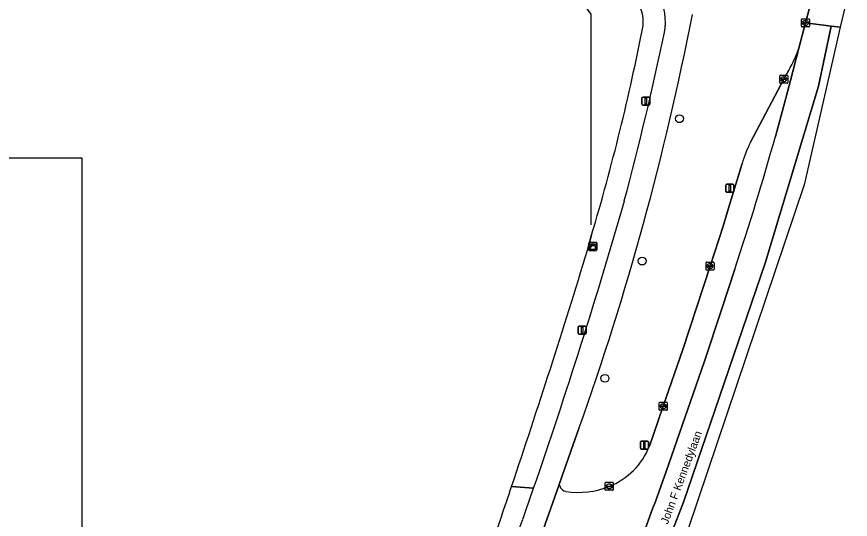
# Model space of a CAD drawing. Extents: x 161241 to 161758, y 384138 to 384885.
# Drawn here: x 161642.2 to 161746.4, y 384754.7 to 384817.5 of the extents above; entities that cross this region are included whole.
import ezdxf

# ---------------------------------------------------------------- set-up
doc = ezdxf.new("R2010")
doc.units = 0
for name, color, linetype in [('IMGEO_Berm_groen', 7, 'Continuous'), ('IMGEO_Boom', 7, 'Continuous'), ('IMGEO_Erf', 7, 'Continuous'), ('IMGEO_Fietspad_gesloten', 7, 'Continuous'), ('IMGEO_Hek', 7, 'Continuous'), ('IMGEO_Kast', 7, 'Continuous'), ('IMGEO_Kolk', 7, 'Continuous'), ('IMGEO_Lichtmast', 7, 'Continuous'), ('IMGEO_Openbare_ruimte_label', 7, 'Continuous'), ('IMGEO_Pand_vergunning_verleend', 7, 'Continuous'), ('IMGEO_Rijbaan_lokaal_gesloten', 7, 'Continuous'), ('IMGEO_Rijbaan_lokaal_open', 7, 'Continuous'), ('IMGEO_Voetpad_open', 7, 'Continuous')]:
    doc.layers.add(name, color=color, linetype=linetype)

msp = doc.modelspace()

# ---------------------------------------------------------------- linework, layer by layer
at = {"layer": 'IMGEO_Berm_groen'}
for points in [[(161740, 384813.52), (161740.82, 384816.69), (161741.28, 384818.41)], [(161733.96, 384801.79), (161738.1, 384809.65), (161738.74, 384810.76)], [(161730.54, 384791.27), (161731.21, 384793.52), (161732.89, 384799.1)], [(161721.31, 384763.82), (161723.04, 384768.79), (161725.49, 384775.9), (161728.89, 384786.3), (161730.54, 384791.27)], [(161712.5, 384766.02), (161710.46, 384760.22), (161709.99, 384758.88), (161710.1, 384758.84)]]:
    msp.add_lwpolyline(points, dxfattribs=at)
for centre, radius, start, end in [((161376.64, 384885.92), 356.62, 340.3527, 348.9764), ((161723.94, 384819.15), 17.01, 330.4533, 340.6775), ((161747.83, 384794.77), 15.55, 153.1574, 163.8286), ((161713, 384767.08), 8.93, 291.639, 338.5775), ((161710.99, 384759.08), 0.921, 194.8928, 263.401), ((161712.5, 384767.94), 9.91, 260.628, 292.4989)]:
    msp.add_arc(centre, radius, start, end, dxfattribs=at)
at = {"layer": 'IMGEO_Boom'}
for centre in [(161725.07, 384804.71), (161720.41, 384786.93), (161715.75, 384772.28)]:
    msp.add_circle(centre, 0.489, dxfattribs=at)
at = {"layer": 'IMGEO_Erf'}
msp.add_lwpolyline([(161713.58, 384788.28), (161714.08, 384790.19)], dxfattribs=at)
for centre, radius, start, end in [((161715.38, 384816.78), 5.16, 355.4845, 65.2299), ((161448.91, 384869.35), 276.74, 343.3794, 348.9636), ((160652.55, 385113.2), 1109.66, 341.37217, 342.97397), ((160591.97, 385133.79), 1173.65, 340.97507, 341.36439)]:
    msp.add_arc(centre, radius, start, end, dxfattribs=at)
at = {"layer": 'IMGEO_Fietspad_gesloten'}
msp.add_lwpolyline([(161707.05, 384750.51), (161709.99, 384758.88), (161710.46, 384760.22), (161712.5, 384766.02)], dxfattribs=at)
for centre, radius, start, end in [((161715.17, 384816.77), 8.14, 350.8431, 58.2286), ((161376.64, 384885.92), 356.62, 340.3527, 348.9764), ((161325, 384899.29), 406.92, 345.0675, 348.1139), ((161030.54, 384992.23), 715.53, 340.93948, 343.95298), ((161038.18, 384989.52), 707.42, 340.61079, 340.94437), ((160913.04, 385019.97), 835.67, 341.22596, 341.48978)]:
    msp.add_arc(centre, radius, start, end, dxfattribs=at)
at = {"layer": 'IMGEO_Hek'}
msp.add_lwpolyline([(161709.2, 384824.32), (161714, 384817.76), (161713.99, 384791.46)], dxfattribs=at)
at = {"layer": 'IMGEO_Kast'}
for p, q in [((161713.81, 384789.26), (161714.65, 384789.26)), ((161714.65, 384789.26), (161713.81, 384789.26)), ((161713.74, 384788.34), (161713.74, 384789.18)), ((161713.74, 384789.18), (161713.74, 384788.34)), ((161714.66, 384788.26), (161713.82, 384788.26)), ((161713.82, 384788.26), (161714.66, 384788.26)), ((161714.74, 384789.19), (161714.74, 384788.35)), ((161714.74, 384788.35), (161714.74, 384789.19))]:
    msp.add_line(p, q, dxfattribs=at)
for points in [[(161713.93, 384789.05), (161714.53, 384789.05), (161714.53, 384788.97), (161713.93, 384788.97), (161713.93, 384789.05)], [(161713.93, 384788.88), (161714.53, 384788.88), (161714.53, 384788.39), (161713.93, 384788.39), (161713.93, 384788.88)]]:
    msp.add_lwpolyline(points, dxfattribs=at)
msp.add_circle((161714.02, 384788.72), 0.0377, dxfattribs=at)
for centre, start, end in [((161713.82, 384789.18), 92.4484, 184.2845), ((161713.82, 384789.18), 92.4484, 184.2845), ((161714.66, 384789.18), 2.4484, 94.2845), ((161714.66, 384789.18), 2.4484, 94.2845), ((161713.82, 384788.34), 182.4484, 274.2845), ((161713.82, 384788.34), 182.4484, 274.2845), ((161714.66, 384788.34), 272.4484, 4.2845), ((161714.66, 384788.34), 272.4484, 4.2845)]:
    msp.add_arc(centre, 0.0779, start, end, dxfattribs=at)
at = {"layer": 'IMGEO_Kolk'}
for p, q in [((161740.32, 384816.26), (161740.32, 384817.11)), ((161740.39, 384817.19), (161741.24, 384817.19)), ((161740.58, 384816.68), (161740.58, 384816.69)), ((161740.62, 384816.73), (161741.02, 384816.73)), ((161741.01, 384816.64), (161740.62, 384816.64)), ((161740.83, 384816.41), (161740.8, 384816.41)), ((161740.81, 384816.97), (161740.83, 384816.97)), ((161741.06, 384816.69), (161741.06, 384816.68)), ((161741.32, 384817.11), (161741.32, 384816.26)), ((161741.24, 384816.19), (161740.39, 384816.19)), ((161737.6, 384809.22), (161737.6, 384810.08)), ((161737.68, 384810.15), (161738.53, 384810.15)), ((161738.6, 384810.08), (161738.6, 384809.22)), ((161738.53, 384809.15), (161737.68, 384809.15)), ((161737.86, 384809.64), (161737.86, 384809.66)), ((161737.9, 384809.69), (161738.3, 384809.69)), ((161738.3, 384809.61), (161737.9, 384809.61)), ((161738.09, 384809.93), (161738.12, 384809.93)), ((161738.11, 384809.37), (161738.09, 384809.37)), ((161738.35, 384809.66), (161738.35, 384809.64)), ((161728.39, 384785.88), (161728.39, 384786.73)), ((161728.46, 384786.8), (161729.31, 384786.8)), ((161728.64, 384786.3), (161728.64, 384786.31)), ((161729.08, 384786.26), (161728.68, 384786.26)), ((161728.69, 384786.35), (161729.08, 384786.35)), ((161728.87, 384786.58), (161728.9, 384786.58)), ((161729.13, 384786.31), (161729.13, 384786.3)), ((161729.39, 384786.73), (161729.39, 384785.88)), ((161729.31, 384785.8), (161728.46, 384785.8)), ((161728.9, 384786.02), (161728.87, 384786.02)), ((161722.54, 384768.36), (161722.54, 384769.22)), ((161722.61, 384769.29), (161723.47, 384769.29)), ((161722.8, 384768.78), (161722.8, 384768.8)), ((161722.84, 384768.83), (161723.24, 384768.83)), ((161723.24, 384768.75), (161722.84, 384768.75)), ((161723.03, 384769.07), (161723.05, 384769.07)), ((161723.05, 384768.51), (161723.03, 384768.51)), ((161723.28, 384768.8), (161723.28, 384768.78)), ((161723.54, 384769.22), (161723.54, 384768.36)), ((161723.47, 384768.29), (161722.61, 384768.29)), ((161715.79, 384758.36), (161715.79, 384759.21)), ((161715.86, 384759.29), (161716.71, 384759.29)), ((161716.28, 384759.07), (161716.3, 384759.07)), ((161716.79, 384759.21), (161716.79, 384758.36)), ((161716.71, 384758.29), (161715.86, 384758.29)), ((161716.05, 384758.78), (161716.05, 384758.79)), ((161716.09, 384758.83), (161716.49, 384758.83)), ((161716.48, 384758.74), (161716.09, 384758.74)), ((161716.3, 384758.51), (161716.27, 384758.51)), ((161716.53, 384758.79), (161716.53, 384758.78))]:
    msp.add_line(p, q, dxfattribs=at)
for points in [[(161740.32, 384816.26), (161740.32, 384817.11)], [(161740.39, 384817.19), (161741.24, 384817.19)], [(161741.32, 384817.11), (161741.32, 384816.26)], [(161741.24, 384816.19), (161740.39, 384816.19)], [(161737.6, 384809.22), (161737.6, 384810.08)], [(161737.68, 384810.15), (161738.53, 384810.15)], [(161738.6, 384810.08), (161738.6, 384809.22)], [(161738.53, 384809.15), (161737.68, 384809.15)], [(161728.39, 384785.88), (161728.39, 384786.73)], [(161728.46, 384786.8), (161729.31, 384786.8)], [(161729.39, 384786.73), (161729.39, 384785.88)], [(161729.31, 384785.8), (161728.46, 384785.8)], [(161722.54, 384768.36), (161722.54, 384769.22)], [(161722.61, 384769.29), (161723.47, 384769.29)], [(161723.54, 384769.22), (161723.54, 384768.36)], [(161723.47, 384768.29), (161722.61, 384768.29)], [(161715.79, 384758.36), (161715.79, 384759.21)], [(161715.86, 384759.29), (161716.71, 384759.29)], [(161716.79, 384759.21), (161716.79, 384758.36)], [(161716.71, 384758.29), (161715.86, 384758.29)]]:
    msp.add_lwpolyline(points, dxfattribs=at)
for centre, radius, start, end in [((161740.39, 384817.11), 0.0765, 91.552, 178.448), ((161740.39, 384817.11), 0.0765, 91.552, 178.448), ((161740.62, 384816.69), 0.0403, 85.8775, 175.7526), ((161740.61, 384816.68), 0.0366, 178.938, 274.7102), ((161741.02, 384816.69), 0.043, 264.8664, 352.4533), ((161741.02, 384816.69), 0.0386, 1.7309, 96.639), ((161741.24, 384817.11), 0.0765, 1.552, 88.448), ((161741.24, 384817.11), 0.0765, 1.552, 88.448), ((161740.39, 384816.26), 0.0765, 181.552, 268.448), ((161740.39, 384816.26), 0.0765, 181.552, 268.448), ((161741.24, 384816.26), 0.0765, 271.552, 358.448), ((161741.24, 384816.26), 0.0765, 271.552, 358.448), ((161737.68, 384810.07), 0.0765, 91.552, 178.448), ((161737.68, 384810.07), 0.0765, 91.552, 178.448), ((161738.53, 384810.07), 0.0765, 1.552, 88.448), ((161738.53, 384810.07), 0.0765, 1.552, 88.448), ((161737.68, 384809.22), 0.0765, 181.552, 268.448), ((161737.68, 384809.22), 0.0765, 181.552, 268.448), ((161737.9, 384809.65), 0.0403, 85.8775, 175.7526), ((161737.9, 384809.64), 0.0366, 178.938, 274.7102), ((161738.31, 384809.65), 0.0386, 1.7309, 96.639), ((161738.3, 384809.65), 0.043, 264.8664, 352.4533), ((161738.53, 384809.22), 0.0765, 271.552, 358.448), ((161738.53, 384809.22), 0.0765, 271.552, 358.448), ((161728.46, 384786.73), 0.0765, 91.552, 178.448), ((161728.46, 384786.73), 0.0765, 91.552, 178.448), ((161728.68, 384786.31), 0.0403, 85.8775, 175.7526), ((161728.68, 384786.3), 0.0366, 178.938, 274.7102), ((161729.09, 384786.31), 0.0386, 1.7309, 96.639), ((161729.09, 384786.3), 0.043, 264.8664, 352.4533), ((161729.31, 384786.73), 0.0765, 1.552, 88.448), ((161729.31, 384786.73), 0.0765, 1.552, 88.448), ((161728.46, 384785.88), 0.0765, 181.552, 268.448), ((161728.46, 384785.88), 0.0765, 181.552, 268.448), ((161729.31, 384785.88), 0.0765, 271.552, 358.448), ((161729.31, 384785.88), 0.0765, 271.552, 358.448), ((161722.62, 384769.22), 0.0765, 91.552, 178.448), ((161722.62, 384769.22), 0.0765, 91.552, 178.448), ((161722.84, 384768.79), 0.0403, 85.8775, 175.7526), ((161722.84, 384768.78), 0.0366, 178.938, 274.7102), ((161723.24, 384768.8), 0.0386, 1.7309, 96.639), ((161723.24, 384768.79), 0.043, 264.8664, 352.4533), ((161723.46, 384769.22), 0.0765, 1.552, 88.448), ((161723.46, 384769.22), 0.0765, 1.552, 88.448), ((161722.62, 384768.37), 0.0765, 181.552, 268.448), ((161722.62, 384768.37), 0.0765, 181.552, 268.448), ((161723.46, 384768.37), 0.0765, 271.552, 358.448), ((161723.46, 384768.37), 0.0765, 271.552, 358.448), ((161715.86, 384759.21), 0.0765, 91.552, 178.448), ((161715.86, 384759.21), 0.0765, 91.552, 178.448), ((161716.71, 384759.21), 0.0765, 1.552, 88.448), ((161716.71, 384759.21), 0.0765, 1.552, 88.448), ((161715.86, 384758.36), 0.0765, 181.552, 268.448), ((161715.86, 384758.36), 0.0765, 181.552, 268.448), ((161716.09, 384758.79), 0.0403, 85.8775, 175.7526), ((161716.08, 384758.78), 0.0366, 178.938, 274.7102), ((161716.49, 384758.79), 0.043, 264.8664, 352.4533), ((161716.49, 384758.79), 0.0386, 1.7309, 96.639), ((161716.71, 384758.36), 0.0765, 271.552, 358.448), ((161716.71, 384758.36), 0.0765, 271.552, 358.448)]:
    msp.add_arc(centre, radius, start, end, dxfattribs=at)
for centre, major_axis, ratio, start_param, end_param in [((161740.8, 384816.69), (-0.387, 0.002), 0.722429, 4.712389, 7.853982), ((161740.83, 384816.69), (-0.39, 0.002), 0.717154, 1.570796, 4.712389), ((161738.09, 384809.65), (-0.387, 0.002), 0.722429, 4.712389, 7.853982), ((161738.11, 384809.65), (-0.39, 0.002), 0.717154, 1.570796, 4.712389), ((161728.87, 384786.3), (-0.387, 0.002), 0.722429, 4.712389, 7.853982), ((161728.9, 384786.3), (-0.39, 0.002), 0.717154, 1.570796, 4.712389), ((161723.03, 384768.79), (-0.387, 0.002), 0.722429, 4.712389, 7.853982), ((161723.05, 384768.79), (-0.39, 0.002), 0.717154, 1.570796, 4.712389), ((161716.27, 384758.79), (-0.387, 0.002), 0.722429, 4.712389, 7.853982), ((161716.3, 384758.79), (-0.39, 0.002), 0.717154, 1.570796, 4.712389)]:
    msp.add_ellipse(centre, major_axis=major_axis, ratio=ratio, start_param=start_param, end_param=end_param, dxfattribs=at)
at = {"layer": 'IMGEO_Lichtmast'}
for p, q in [((161720.38, 384806.51), (161720.38, 384807.31)), ((161720.38, 384807.31), (161720.38, 384806.51)), ((161720.48, 384807.41), (161721.27, 384807.41)), ((161721.27, 384807.41), (161720.48, 384807.41)), ((161721.37, 384807.31), (161721.37, 384806.51)), ((161721.37, 384806.51), (161721.37, 384807.31)), ((161721.27, 384806.41), (161720.48, 384806.41)), ((161720.48, 384806.41), (161721.27, 384806.41)), ((161730.96, 384796.52), (161731.75, 384796.52)), ((161731.75, 384796.52), (161730.96, 384796.52)), ((161730.86, 384795.62), (161730.86, 384796.42)), ((161730.86, 384796.42), (161730.86, 384795.62)), ((161731.75, 384795.52), (161730.96, 384795.52)), ((161730.96, 384795.52), (161731.75, 384795.52)), ((161731.85, 384796.42), (161731.85, 384795.62)), ((161731.85, 384795.62), (161731.85, 384796.42)), ((161712.51, 384778.8), (161713.3, 384778.8)), ((161713.3, 384778.8), (161712.51, 384778.8)), ((161712.41, 384777.9), (161712.41, 384778.7)), ((161712.41, 384778.7), (161712.41, 384777.9)), ((161713.3, 384777.8), (161712.51, 384777.8)), ((161712.51, 384777.8), (161713.3, 384777.8)), ((161713.4, 384778.7), (161713.4, 384777.9)), ((161713.4, 384777.9), (161713.4, 384778.7)), ((161720.19, 384763.54), (161720.19, 384764.33)), ((161720.19, 384764.33), (161720.19, 384763.54)), ((161720.29, 384764.43), (161721.08, 384764.43)), ((161721.08, 384764.43), (161720.29, 384764.43)), ((161721.18, 384764.33), (161721.18, 384763.54)), ((161721.18, 384763.54), (161721.18, 384764.33)), ((161721.08, 384763.44), (161720.29, 384763.44)), ((161720.29, 384763.44), (161721.08, 384763.44))]:
    msp.add_line(p, q, dxfattribs=at)
for points in [[(161720.8, 384807.29), (161720.95, 384807.29), (161720.95, 384806.54), (161720.8, 384806.54), (161720.8, 384807.29)], [(161731.28, 384796.4), (161731.43, 384796.4), (161731.43, 384795.65), (161731.28, 384795.65), (161731.28, 384796.4)], [(161712.83, 384778.68), (161712.98, 384778.68), (161712.98, 384777.93), (161712.83, 384777.93), (161712.83, 384778.68)], [(161720.61, 384764.31), (161720.76, 384764.31), (161720.76, 384763.56), (161720.61, 384763.56), (161720.61, 384764.31)]]:
    msp.add_lwpolyline(points, dxfattribs=at)
for centre, start, end in [((161720.48, 384807.31), 90, 180), ((161720.48, 384807.31), 90, 180), ((161721.27, 384807.31), 0, 90), ((161721.27, 384807.31), 360, 90), ((161720.48, 384806.51), 180, 270), ((161720.48, 384806.51), 180, 270), ((161721.27, 384806.51), 270, 0), ((161721.27, 384806.51), 270, 0), ((161730.96, 384796.42), 90, 180), ((161730.96, 384796.42), 90, 180), ((161731.75, 384796.42), 0, 90), ((161731.75, 384796.42), 360, 90), ((161730.96, 384795.62), 180, 270), ((161730.96, 384795.62), 180, 270), ((161731.75, 384795.62), 270, 0), ((161731.75, 384795.62), 270, 0), ((161712.51, 384778.7), 90, 180), ((161712.51, 384778.7), 90, 180), ((161713.3, 384778.7), 0, 90), ((161713.3, 384778.7), 360, 90), ((161712.51, 384777.9), 180, 270), ((161712.51, 384777.9), 180, 270), ((161713.3, 384777.9), 270, 0), ((161713.3, 384777.9), 270, 0), ((161720.29, 384764.33), 90, 180), ((161720.29, 384764.33), 90, 180), ((161721.08, 384764.33), 0, 90), ((161721.08, 384764.33), 360, 90), ((161720.29, 384763.54), 180, 270), ((161720.29, 384763.54), 180, 270), ((161721.08, 384763.54), 270, 0), ((161721.08, 384763.54), 270, 0)]:
    msp.add_arc(centre, 0.1, start, end, dxfattribs=at)
at = {"layer": 'IMGEO_Pand_vergunning_verleend'}
msp.add_lwpolyline([(161594.18, 384722.29), (161594.18, 384737.51), (161607.77, 384737.51), (161607.77, 384799.84), (161650.38, 384799.84), (161650.38, 384737.08), (161656.32, 384737.08), (161656.32, 384722.29)], close=True, dxfattribs=at)
at = {"layer": 'IMGEO_Rijbaan_lokaal_gesloten'}
msp.add_lwpolyline([(161745.21, 384816.14), (161746.43, 384821.45), (161742.04, 384822.08), (161741.28, 384818.41), (161740.82, 384816.69), (161744.05, 384816.28)], close=True, dxfattribs=at)
for points in [[(161742.45, 384808.76), (161744.05, 384816.28), (161740.82, 384816.69), (161740, 384813.52), (161738.95, 384809.48), (161738.18, 384806.66), (161737.06, 384802.5)], [(161659.74, 384606.29), (161679.56, 384646.07), (161706.08, 384702.62), (161726.15, 384753.41), (161740.76, 384796.63), (161745.21, 384816.14), (161744.05, 384816.28), (161742.45, 384808.76), (161735.78, 384786.65), (161725.58, 384756.83), (161716.26, 384732.83), (161712.72, 384722.3), (161707.13, 384707.91), (161694.57, 384679.26), (161680.18, 384650.09), (161667.1, 384624.19), (161658.51, 384607.26), (161659.74, 384606.29)], [(161737.06, 384802.5), (161738.18, 384806.66), (161738.95, 384809.48), (161740, 384813.52)], [(161738.74, 384810.76), (161738.1, 384809.65), (161733.96, 384801.79)], [(161694.57, 384679.26), (161707.13, 384707.91), (161712.72, 384722.3), (161716.26, 384732.83), (161725.58, 384756.83), (161735.78, 384786.65), (161742.45, 384808.76)], [(161732.89, 384799.1), (161731.21, 384793.52), (161730.54, 384791.27), (161728.89, 384786.3), (161725.49, 384775.9), (161723.04, 384768.79), (161721.31, 384763.82)], [(161732, 384785.93), (161730.38, 384780.97), (161728.14, 384774.32), (161726.12, 384768.43), (161723.42, 384760.65), (161722.08, 384756.88), (161721.7, 384755.96), (161712.78, 384731.32), (161700.18, 384699.41), (161692.45, 384682.11)], [(161721.7, 384755.96), (161722.08, 384756.88), (161723.42, 384760.65), (161726.12, 384768.43), (161728.14, 384774.32), (161730.38, 384780.97), (161732, 384785.93)], [(161710.1, 384758.84), (161709.99, 384758.88), (161707.05, 384750.51)], [(161692.45, 384682.11), (161700.18, 384699.41), (161712.78, 384731.32), (161721.7, 384755.96)]]:
    msp.add_lwpolyline(points, dxfattribs=at)
for centre, radius, start, end in [((161723.94, 384819.15), 17.01, 330.4533, 340.6775), ((161366.38, 384906.58), 385.01, 341.7382, 344.3165), ((161366.38, 384906.58), 385.01, 341.7382, 344.3165), ((161747.83, 384794.77), 15.55, 153.1574, 163.8286), ((161713, 384767.08), 8.93, 291.639, 338.5775), ((161710.99, 384759.08), 0.921, 194.8928, 263.401), ((161712.5, 384767.94), 9.91, 260.628, 292.4989)]:
    msp.add_arc(centre, radius, start, end, dxfattribs=at)
at = {"layer": 'IMGEO_Rijbaan_lokaal_open'}
msp.add_lwpolyline([(161706.84, 384758.56), (161704.08, 384758.75)], dxfattribs=at)
for centre, radius, start, end in [((160591.97, 385133.79), 1173.65, 340.97507, 341.36439), ((161038.18, 384989.52), 707.42, 340.61079, 340.94437), ((160913.04, 385019.97), 835.67, 341.22596, 341.48978)]:
    msp.add_arc(centre, radius, start, end, dxfattribs=at)
at = {"layer": 'IMGEO_Voetpad_open'}
for points in [[(161714.08, 384790.19), (161713.58, 384788.28)], [(161704.08, 384758.75), (161706.84, 384758.56)]]:
    msp.add_lwpolyline(points, dxfattribs=at)
for centre, radius, start, end in [((161715.17, 384816.77), 8.14, 350.8431, 58.2286), ((161715.38, 384816.78), 5.16, 355.4845, 65.2299), ((161448.91, 384869.35), 276.74, 343.3794, 348.9636), ((161325, 384899.29), 406.92, 345.0675, 348.1139), ((161030.54, 384992.23), 715.53, 340.93948, 343.95298), ((160652.55, 385113.2), 1109.66, 341.37217, 342.97397)]:
    msp.add_arc(centre, radius, start, end, dxfattribs=at)

# ---------------------------------------------------------------- texts
at = {"layer": 'IMGEO_Openbare_ruimte_label'}
msp.add_text('John F Kennedylaan', height=1, rotation=69.5177, dxfattribs=at).set_placement((161723.62, 384753.99))

doc.saveas('drawing.dxf')
